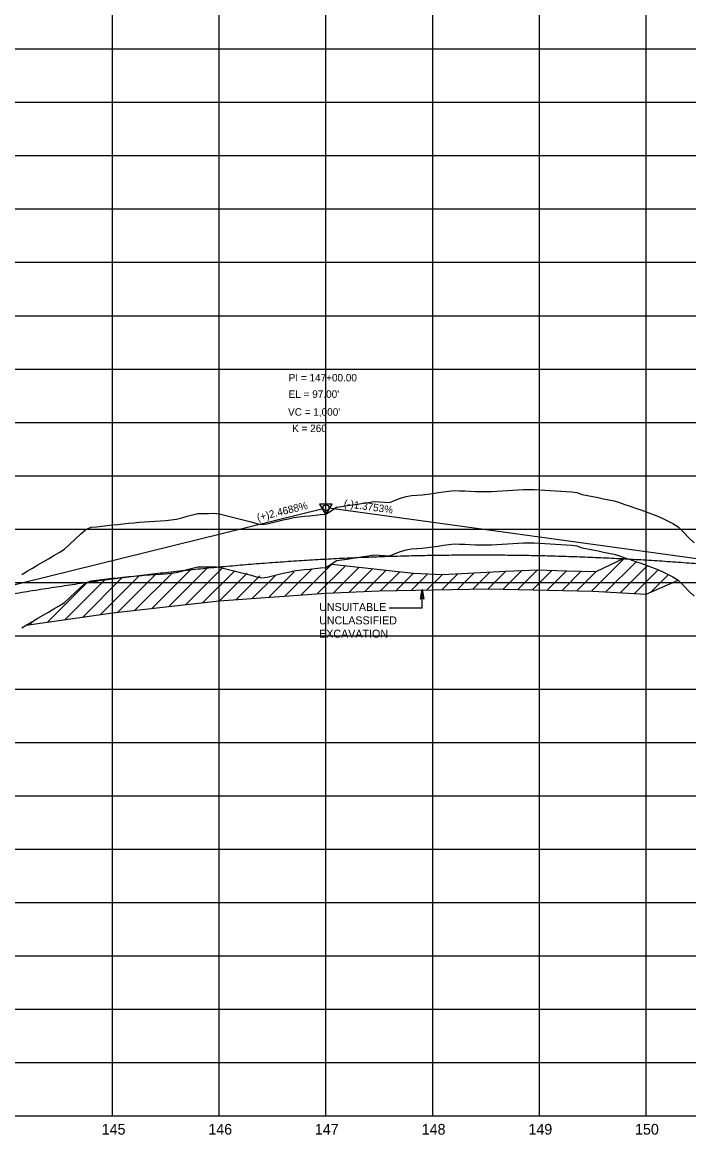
# Model space of a CAD drawing. Extents: x 2345490 to 2436403, y 465165 to 573888.
# Drawn here: x 2394737 to 2395362, y 564259 to 565302 of the extents above; entities that cross this region are included whole.
import ezdxf

# ---------------------------------------------------------------- set-up
doc = ezdxf.new("R2010")
doc.units = 0
for name, color, linetype in [('Old_Level_1', 7, 'Continuous'), ('Old_Level_2', 7, 'Continuous'), ('Old_Level_5', 7, 'Continuous'), ('Old_Level_57', 7, 'Continuous'), ('Old_Level_62', 7, 'Continuous'), ('Old_Level_63', 7, 'Continuous')]:
    doc.layers.add(name, color=color, linetype=linetype)

msp = doc.modelspace()

# ---------------------------------------------------------------- linework, layer by layer
at = {"layer": 'Old_Level_1'}
for points in [[(2394871.5425, 564784.70325), (2394876.5425, 564785.0805), (2394881.5425, 564785.7525), (2394886.5425, 564787.1625), (2394891.5425, 564788.57475), (2394896.5425, 564789.98975), (2394901.5425, 564791.04825), (2394906.5425, 564791.167), (2394911.5425, 564791.2875), (2394916.5425, 564791.41), (2394921.5425, 564790.949), (2394926.5425, 564789.65), (2394931.5425, 564788.353), (2394936.5425, 564787.05825), (2394941.5425, 564785.76575), (2394946.5425, 564784.47525), (2394951.5425, 564783.187), (2394956.5425, 564781.90125), (2394961.5425, 564780.70675), (2394966.5425, 564781.328), (2394971.5425, 564782.704), (2394976.5425, 564784.05575), (2394981.5425, 564785.136), (2394986.5425, 564786.217), (2394991.5425, 564787.29825), (2394996.5425, 564788.06675), (2395001.5425, 564788.567), (2395006.5425, 564789.067), (2395011.5425, 564789.5665), (2395016.5425, 564790.0655), (2395021.5425, 564790.564), (2395026.5425, 564793.6885), (2395031.5425, 564796.93725), (2395036.5425, 564797.71025), (2395041.5425, 564798.48375), (2395046.5425, 564799.25775), (2395051.5425, 564800.0325), (2395056.5425, 564800.8075), (2395061.5425, 564801.58325), (2395066.5425, 564802.3595), (2395071.5425, 564802.136), (2395076.5425, 564801.74725), (2395081.5425, 564801.35525), (2395086.5425, 564803.53375), (2395091.5425, 564805.56275), (2395096.5425, 564807.12325), (2395101.5425, 564807.87825), (2395106.5425, 564808.23575), (2395111.5425, 564808.755), (2395116.5425, 564809.3935), (2395121.5425, 564810.03125), (2395126.5425, 564810.668), (2395131.5425, 564811.30375), (2395136.5425, 564811.93875), (2395141.5425, 564812.57275), (2395146.5425, 564812.49925), (2395151.5425, 564812.27), (2395156.5425, 564812.0395), (2395161.5425, 564811.80775), (2395166.5425, 564811.702), (2395171.5425, 564811.662), (2395176.5425, 564811.716), (2395181.5425, 564812.02925), (2395186.5425, 564812.342), (2395191.5425, 564812.65425), (2395196.5425, 564812.96625), (2395201.5425, 564813.27775), (2395206.5425, 564813.58875), (2395211.5425, 564813.769), (2395216.5425, 564813.54275), (2395221.5425, 564813.259), (2395226.5425, 564812.97425), (2395231.5425, 564812.68825), (2395236.5425, 564812.40125), (2395241.5425, 564812.113), (2395246.5425, 564811.82375), (2395251.5425, 564811.53325), (2395256.5425, 564810.6815), (2395261.5425, 564809.07625), (2395266.5425, 564808.05275), (2395271.5425, 564807.02675), (2395276.5425, 564805.99875), (2395281.5425, 564804.9685), (2395286.5425, 564803.93625), (2395291.5425, 564802.9015), (2395296.5425, 564801.33775), (2395301.5425, 564799.687), (2395306.5425, 564797.937), (2395311.5425, 564796.18425), (2395316.5425, 564794.429), (2395321.5425, 564792.61175), (2395326.5425, 564790.741), (2395331.5425, 564788.86775), (2395336.5425, 564786.9), (2395341.5425, 564784.40775), (2395346.5425, 564781.913), (2395351.5425, 564778.7435), (2395356.5425, 564773.543), (2395361.5425, 564768.313), (2395366.5425, 564763.7145)], [(2394736.5425, 564733.9965), (2394741.5425, 564737.0815), (2394746.5425, 564739.9885), (2394751.5425, 564742.898), (2394756.5425, 564745.81425), (2394761.5425, 564748.78375), (2394766.5425, 564751.75575), (2394771.5425, 564754.72975), (2394776.5425, 564757.7065), (2394781.5425, 564762.3775), (2394786.5425, 564767.137), (2394791.5425, 564771.89975), (2394796.5425, 564776.12), (2394801.5425, 564778.18225), (2394806.5425, 564778.72625), (2394811.5425, 564779.27325), (2394816.5425, 564779.82325), (2394821.5425, 564780.376), (2394826.5425, 564780.932), (2394831.5425, 564781.4905), (2394836.5425, 564782.057), (2394841.5425, 564782.4995), (2394846.5425, 564782.85975), (2394851.5425, 564783.22275), (2394856.5425, 564783.58875), (2394861.5425, 564783.9575), (2394866.5425, 564784.329), (2394871.5425, 564784.70325)]]:
    msp.add_lwpolyline(points, dxfattribs=at)
at = {"layer": 'Old_Level_2'}
for p, q in [((2394521.5425, 564723.0965), (2395018.87275, 564845.87475)), ((2395521.5425, 564777.76925), (2395024.267, 564846.15925))]:
    msp.add_line(p, q, dxfattribs=at)
msp.add_lwpolyline([(2395027.299, 564849.86625), (2395015.5565, 564849.85175), (2395021.44, 564839.7335)], close=True, dxfattribs=at)
msp.add_circle((2395021.5425, 564846.534), 2.75, dxfattribs=at)
msp.add_spline([(2394521.5425, 564723.0965), (2394541.5425, 564727.957), (2394561.5425, 564732.66375), (2394581.5425, 564737.217), (2394601.5425, 564741.61625), (2394621.5425, 564745.86175), (2394641.5425, 564749.95375), (2394661.5425, 564753.89175), (2394681.5425, 564757.676), (2394701.5425, 564761.3065), (2394721.5425, 564764.78325), (2394741.5425, 564768.10625), (2394761.5425, 564771.2755), (2394781.5425, 564774.291), (2394801.5425, 564777.15275), (2394821.5425, 564779.86075), (2394841.5425, 564782.41475), (2394861.5425, 564784.81525), (2394881.5425, 564787.062), (2394901.5425, 564789.155), (2394921.5425, 564791.094), (2394941.5425, 564792.8795), (2394961.5425, 564794.511), (2394981.5425, 564795.989), (2395001.5425, 564797.313), (2395021.5425, 564798.48325), (2395041.5425, 564799.5), (2395061.5425, 564800.36275), (2395081.5425, 564801.07175), (2395101.5425, 564801.627), (2395121.5425, 564802.0285), (2395141.5425, 564802.27625), (2395161.5425, 564802.37025), (2395181.5425, 564802.3105), (2395201.5425, 564802.097), (2395221.5425, 564801.72975), (2395241.5425, 564801.20875), (2395261.5425, 564800.534), (2395281.5425, 564799.7055), (2395301.5425, 564798.723), (2395321.5425, 564797.587), (2395341.5425, 564796.297), (2395361.5425, 564794.8535), (2395381.5425, 564793.256), (2395401.5425, 564791.505), (2395421.5425, 564789.6), (2395441.5425, 564787.5415), (2395461.5425, 564785.329), (2395481.5425, 564782.96275), (2395501.5425, 564780.443), (2395521.5425, 564777.76925)], degree=3, dxfattribs=at)
at = {"layer": 'Old_Level_5'}
for p, q in [((2395270.33281, 564768.24449), (2395301.66586, 564799.57754)), ((2395274.80652, 564786.86033), (2395301.66586, 564799.57754)), ((2394858.54911, 564752.44059), (2394895.71545, 564789.60693)), ((2394874.58855, 564754.33789), (2394911.54002, 564791.28936)), ((2394890.34967, 564755.95687), (2394924.23505, 564789.84226)), ((2394983.3402, 564764.09459), (2395008.50813, 564789.26252)), ((2394998.45417, 564765.06642), (2395027.02319, 564793.63545)), ((2395013.56813, 564766.03825), (2395039.75964, 564792.22976)), ((2395027.02319, 564793.63545), (2395077.96899, 564788.0127)), ((2395028.53824, 564766.86623), (2395052.49609, 564790.82407)), ((2395043.34769, 564767.53354), (2395065.23254, 564789.41839)), ((2395283.81031, 564767.57985), (2395312.18247, 564795.95201)), ((2395297.26568, 564766.89309), (2395322.5591, 564792.18651)), ((2394777.04451, 564741.64666), (2394815.06008, 564779.66224)), ((2394793.51106, 564743.97108), (2394830.93053, 564781.39055)), ((2394809.97762, 564746.2955), (2394846.5433, 564782.86118)), ((2394826.33688, 564748.51263), (2394861.80377, 564783.97952)), ((2394842.443, 564750.47661), (2394877.27067, 564785.30428)), ((2394906.11079, 564757.57585), (2394935.99438, 564787.45944)), ((2394921.865, 564759.18793), (2394947.77248, 564785.09541)), ((2394937.29559, 564760.47638), (2394959.55058, 564782.73138)), ((2394952.72618, 564761.76484), (2394973.78789, 564782.82655)), ((2394968.15676, 564763.05329), (2394991.61775, 564786.51428)), ((2395058.15714, 564768.20086), (2395077.96899, 564788.0127)), ((2395072.92486, 564768.82644), (2395090.70544, 564786.60701)), ((2395077.96899, 564788.0127), (2395103.44188, 564785.20133)), ((2395087.30031, 564769.05975), (2395103.44188, 564785.20133)), ((2395101.67576, 564769.29306), (2395116.41406, 564784.03137)), ((2395103.44188, 564785.20133), (2395130.63543, 564784.1106)), ((2395116.05121, 564769.52638), (2395130.63543, 564784.1106)), ((2395130.42666, 564769.75969), (2395145.51779, 564784.85082)), ((2395130.63543, 564784.1106), (2395160.40016, 564785.59105)), ((2395144.8021, 564769.993), (2395160.40016, 564785.59105)), ((2395159.17755, 564770.22632), (2395175.28252, 564786.33128)), ((2395160.40016, 564785.59105), (2395190.16489, 564787.07151)), ((2395173.49576, 564770.40239), (2395190.16489, 564787.07151)), ((2395187.46192, 564770.22642), (2395205.04725, 564787.81174)), ((2395190.16489, 564787.07151), (2395219.6368, 564788.25916)), ((2395201.42809, 564770.05044), (2395219.6368, 564788.25916)), ((2395215.39425, 564769.87447), (2395233.54455, 564788.02477)), ((2395219.6368, 564788.25916), (2395246.98684, 564787.32492)), ((2395229.21478, 564769.55287), (2395246.98684, 564787.32492)), ((2395242.92079, 564769.11674), (2395260.42913, 564786.62508)), ((2395246.98684, 564787.32492), (2395274.80652, 564786.86033)), ((2395256.6268, 564768.68062), (2395274.80652, 564786.86033)), ((2395310.72106, 564766.20633), (2395332.83773, 564788.323)), ((2395321.5425, 564765.654), (2395351.5425, 564778.7435)), ((2395326.4537, 564767.79684), (2395342.55729, 564783.90042)), ((2394760.57796, 564739.32224), (2394797.96061, 564776.7049)), ((2395021.5425, 564766.551), (2395071.5425, 564768.804)), ((2395071.5425, 564768.804), (2395173.49576, 564770.40239)), ((2395111.72974, 564752.75123), (2395111.72974, 564769.90837)), ((2395173.49576, 564770.40239), (2395271.5425, 564768.206)), ((2395271.5425, 564768.206), (2395321.5425, 564765.654)), ((2394821.5425, 564747.928), (2394921.5425, 564759.161)), ((2394921.5425, 564759.161), (2395021.5425, 564766.551)), ((2394740.60458, 564736.5028), (2394821.5425, 564747.928)), ((2395080.84689, 564752.75123), (2395111.72974, 564752.75123)), ((2394744.1114, 564736.99783), (2394747.89527, 564740.7817))]:
    msp.add_line(p, q, dxfattribs=at)
msp.add_lwpolyline([(2395110.17974, 564760.90837), (2395111.72974, 564769.90837), (2395113.32974, 564760.85837), (2395111.72974, 564762.00837)], close=True, dxfattribs=at)
at = {"layer": 'Old_Level_57'}
for p, q in [((2394821.54225, 564276.534), (2394821.54225, 566615.2835)), ((2394921.5425, 564276.534), (2394921.5425, 566615.2835)), ((2395021.54225, 564276.534), (2395021.54225, 566615.2835)), ((2395121.54225, 564276.534), (2395121.54225, 566615.2835)), ((2395221.54225, 564276.534), (2395221.54225, 566615.2835)), ((2395321.54225, 564276.534), (2395321.54225, 566615.2835)), ((2381271.5425, 565276.534), (2410861.12275, 565276.534)), ((2381271.5425, 565226.534), (2410861.12275, 565226.534)), ((2381271.5425, 565176.534), (2410861.12275, 565176.534)), ((2381271.5425, 565126.534), (2410861.12275, 565126.534)), ((2381271.5425, 565076.534), (2410861.12275, 565076.534)), ((2381271.5425, 565026.534), (2410861.12275, 565026.534)), ((2381271.5425, 564976.534), (2410861.12275, 564976.534)), ((2381271.5425, 564926.534), (2410861.12275, 564926.534)), ((2381271.5425, 564876.534), (2410861.12275, 564876.534)), ((2381271.5425, 564826.534), (2410861.12275, 564826.534)), ((2381271.54275, 564776.534), (2410861.123, 564776.534)), ((2381271.5425, 564726.534), (2410861.12275, 564726.534)), ((2381271.54275, 564676.534), (2410861.123, 564676.534)), ((2381271.5425, 564626.534), (2410861.12275, 564626.534)), ((2381271.54275, 564576.534), (2410861.123, 564576.534)), ((2381271.5425, 564526.534), (2410861.12275, 564526.534)), ((2381271.54275, 564476.534), (2410861.123, 564476.534)), ((2381271.5425, 564426.534), (2410861.12275, 564426.534)), ((2381271.54275, 564376.534), (2410861.123, 564376.534)), ((2381271.5425, 564326.534), (2410861.12275, 564326.534)), ((2381271.54275, 564276.534), (2410861.123, 564276.534))]:
    msp.add_line(p, q, dxfattribs=at)
at = {"layer": 'Old_Level_63'}
msp.add_line((2381321.5425, 564276.534), (2406689.937, 564276.534), dxfattribs=at)
for points in [[(2394871.5425, 564834.703), (2394876.5425, 564835.08025), (2394881.5425, 564835.75225), (2394886.5425, 564837.16225), (2394891.5425, 564838.5745), (2394896.5425, 564839.9895), (2394901.5425, 564841.048), (2394906.5425, 564841.16675), (2394911.5425, 564841.28725), (2394916.5425, 564841.40975), (2394921.5425, 564840.94875), (2394926.5425, 564839.64975), (2394931.5425, 564838.35275), (2394936.5425, 564837.058), (2394941.5425, 564835.7655), (2394946.5425, 564834.475), (2394951.5425, 564833.18675), (2394956.5425, 564831.901), (2394961.5425, 564830.7065), (2394966.5425, 564831.32775), (2394971.5425, 564832.70375), (2394976.5425, 564834.0555), (2394981.5425, 564835.13575), (2394986.5425, 564836.21675), (2394991.5425, 564837.298), (2394996.5425, 564838.0665), (2395001.5425, 564838.56675), (2395006.5425, 564839.06675), (2395011.5425, 564839.56625), (2395016.5425, 564840.06525), (2395021.5425, 564840.56375), (2395026.5425, 564843.68825), (2395031.5425, 564846.937), (2395036.5425, 564847.71), (2395041.5425, 564848.4835), (2395046.5425, 564849.2575), (2395051.5425, 564850.03225), (2395056.5425, 564850.80725), (2395061.5425, 564851.583), (2395066.5425, 564852.35925), (2395071.5425, 564852.13575), (2395076.5425, 564851.747), (2395081.5425, 564851.355), (2395086.5425, 564853.5335), (2395091.5425, 564855.5625), (2395096.5425, 564857.123), (2395101.5425, 564857.878), (2395106.5425, 564858.2355), (2395111.5425, 564858.75475), (2395116.5425, 564859.39325), (2395121.5425, 564860.031), (2395126.5425, 564860.66775), (2395131.5425, 564861.3035), (2395136.5425, 564861.9385), (2395141.5425, 564862.5725), (2395146.5425, 564862.499), (2395151.5425, 564862.26975), (2395156.5425, 564862.03925), (2395161.5425, 564861.8075), (2395166.5425, 564861.70175), (2395171.5425, 564861.66175), (2395176.5425, 564861.71575), (2395181.5425, 564862.029), (2395186.5425, 564862.34175), (2395191.5425, 564862.654), (2395196.5425, 564862.966), (2395201.5425, 564863.2775), (2395206.5425, 564863.5885), (2395211.5425, 564863.76875), (2395216.5425, 564863.5425), (2395221.5425, 564863.25875), (2395226.5425, 564862.974), (2395231.5425, 564862.688), (2395236.5425, 564862.401), (2395241.5425, 564862.11275), (2395246.5425, 564861.8235), (2395251.5425, 564861.533), (2395256.5425, 564860.68125), (2395261.5425, 564859.076), (2395266.5425, 564858.0525), (2395271.5425, 564857.0265), (2395276.5425, 564855.9985), (2395281.5425, 564854.96825), (2395286.5425, 564853.936), (2395291.5425, 564852.90125), (2395296.5425, 564851.3375), (2395301.5425, 564849.68675), (2395306.5425, 564847.93675), (2395311.5425, 564846.184), (2395316.5425, 564844.42875), (2395321.5425, 564842.6115), (2395326.5425, 564840.74075), (2395331.5425, 564838.8675), (2395336.5425, 564836.89975), (2395341.5425, 564834.4075), (2395346.5425, 564831.91275), (2395351.5425, 564828.74325), (2395356.5425, 564823.54275), (2395361.5425, 564818.31275), (2395366.5425, 564813.71425)], [(2394736.5425, 564783.99625), (2394741.5425, 564787.08125), (2394746.5425, 564789.98825), (2394751.5425, 564792.89775), (2394756.5425, 564795.814), (2394761.5425, 564798.7835), (2394766.5425, 564801.7555), (2394771.5425, 564804.7295), (2394776.5425, 564807.70625), (2394781.5425, 564812.37725), (2394786.5425, 564817.13675), (2394791.5425, 564821.8995), (2394796.5425, 564826.11975), (2394801.5425, 564828.182), (2394806.5425, 564828.726), (2394811.5425, 564829.273), (2394816.5425, 564829.823), (2394821.5425, 564830.37575), (2394826.5425, 564830.93175), (2394831.5425, 564831.49025), (2394836.5425, 564832.05675), (2394841.5425, 564832.49925), (2394846.5425, 564832.8595), (2394851.5425, 564833.2225), (2394856.5425, 564833.5885), (2394861.5425, 564833.95725), (2394866.5425, 564834.32875), (2394871.5425, 564834.703)]]:
    msp.add_lwpolyline(points, dxfattribs=at)

# ---------------------------------------------------------------- texts
at = {"layer": 'Old_Level_2'}
for s, height, p in [('PI = 147+00.00', 7.0000005, (2394986.54275, 564964.89525)), ("EL = 97.00'", 7.0000005, (2394986.5425, 564949.534)), ("VC = 1,000'", 7.0000005, (2394985.98875, 564932.8045)), ('K = 260', 7.000001, (2394989.8535, 564917.42625))]:
    msp.add_text(s, height=height, dxfattribs=at).set_placement(p)
for s, rotation, p in [('(+)2.4688%', 13.86760278, (2394957.75325, 564833.876)), ('(-)1.3753%', 352.16926944, (2395037.99425, 564847.2995))]:
    msp.add_text(s, height=7.000001, rotation=rotation, dxfattribs=at).set_placement(p)
at = {"layer": 'Old_Level_5'}
for s, p in [('UNSUITABLE', (2395015.1003, 564749.72171)), ('UNCLASSIFIED', (2395015.1003, 564737.22171)), ('EXCAVATION', (2395015.1003, 564724.72171))]:
    msp.add_text(s, height=7.5, dxfattribs=at).set_placement(p)
at = {"layer": 'Old_Level_62'}
for s, p in [('145', (2394811.329, 564259.034)), ('146', (2394911.27, 564259.034)), ('147', (2395011.1275, 564259.034)), ('148', (2395111.25325, 564259.034)), ('149', (2395211.2955, 564259.034)), ('150', (2395311.1715, 564259.034))]:
    msp.add_text(s, height=10.000001, dxfattribs=at).set_placement(p)

doc.saveas('drawing.dxf')
